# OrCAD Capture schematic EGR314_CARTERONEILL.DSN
size B; title: Audio Sensor Team 203 Carter ONeill
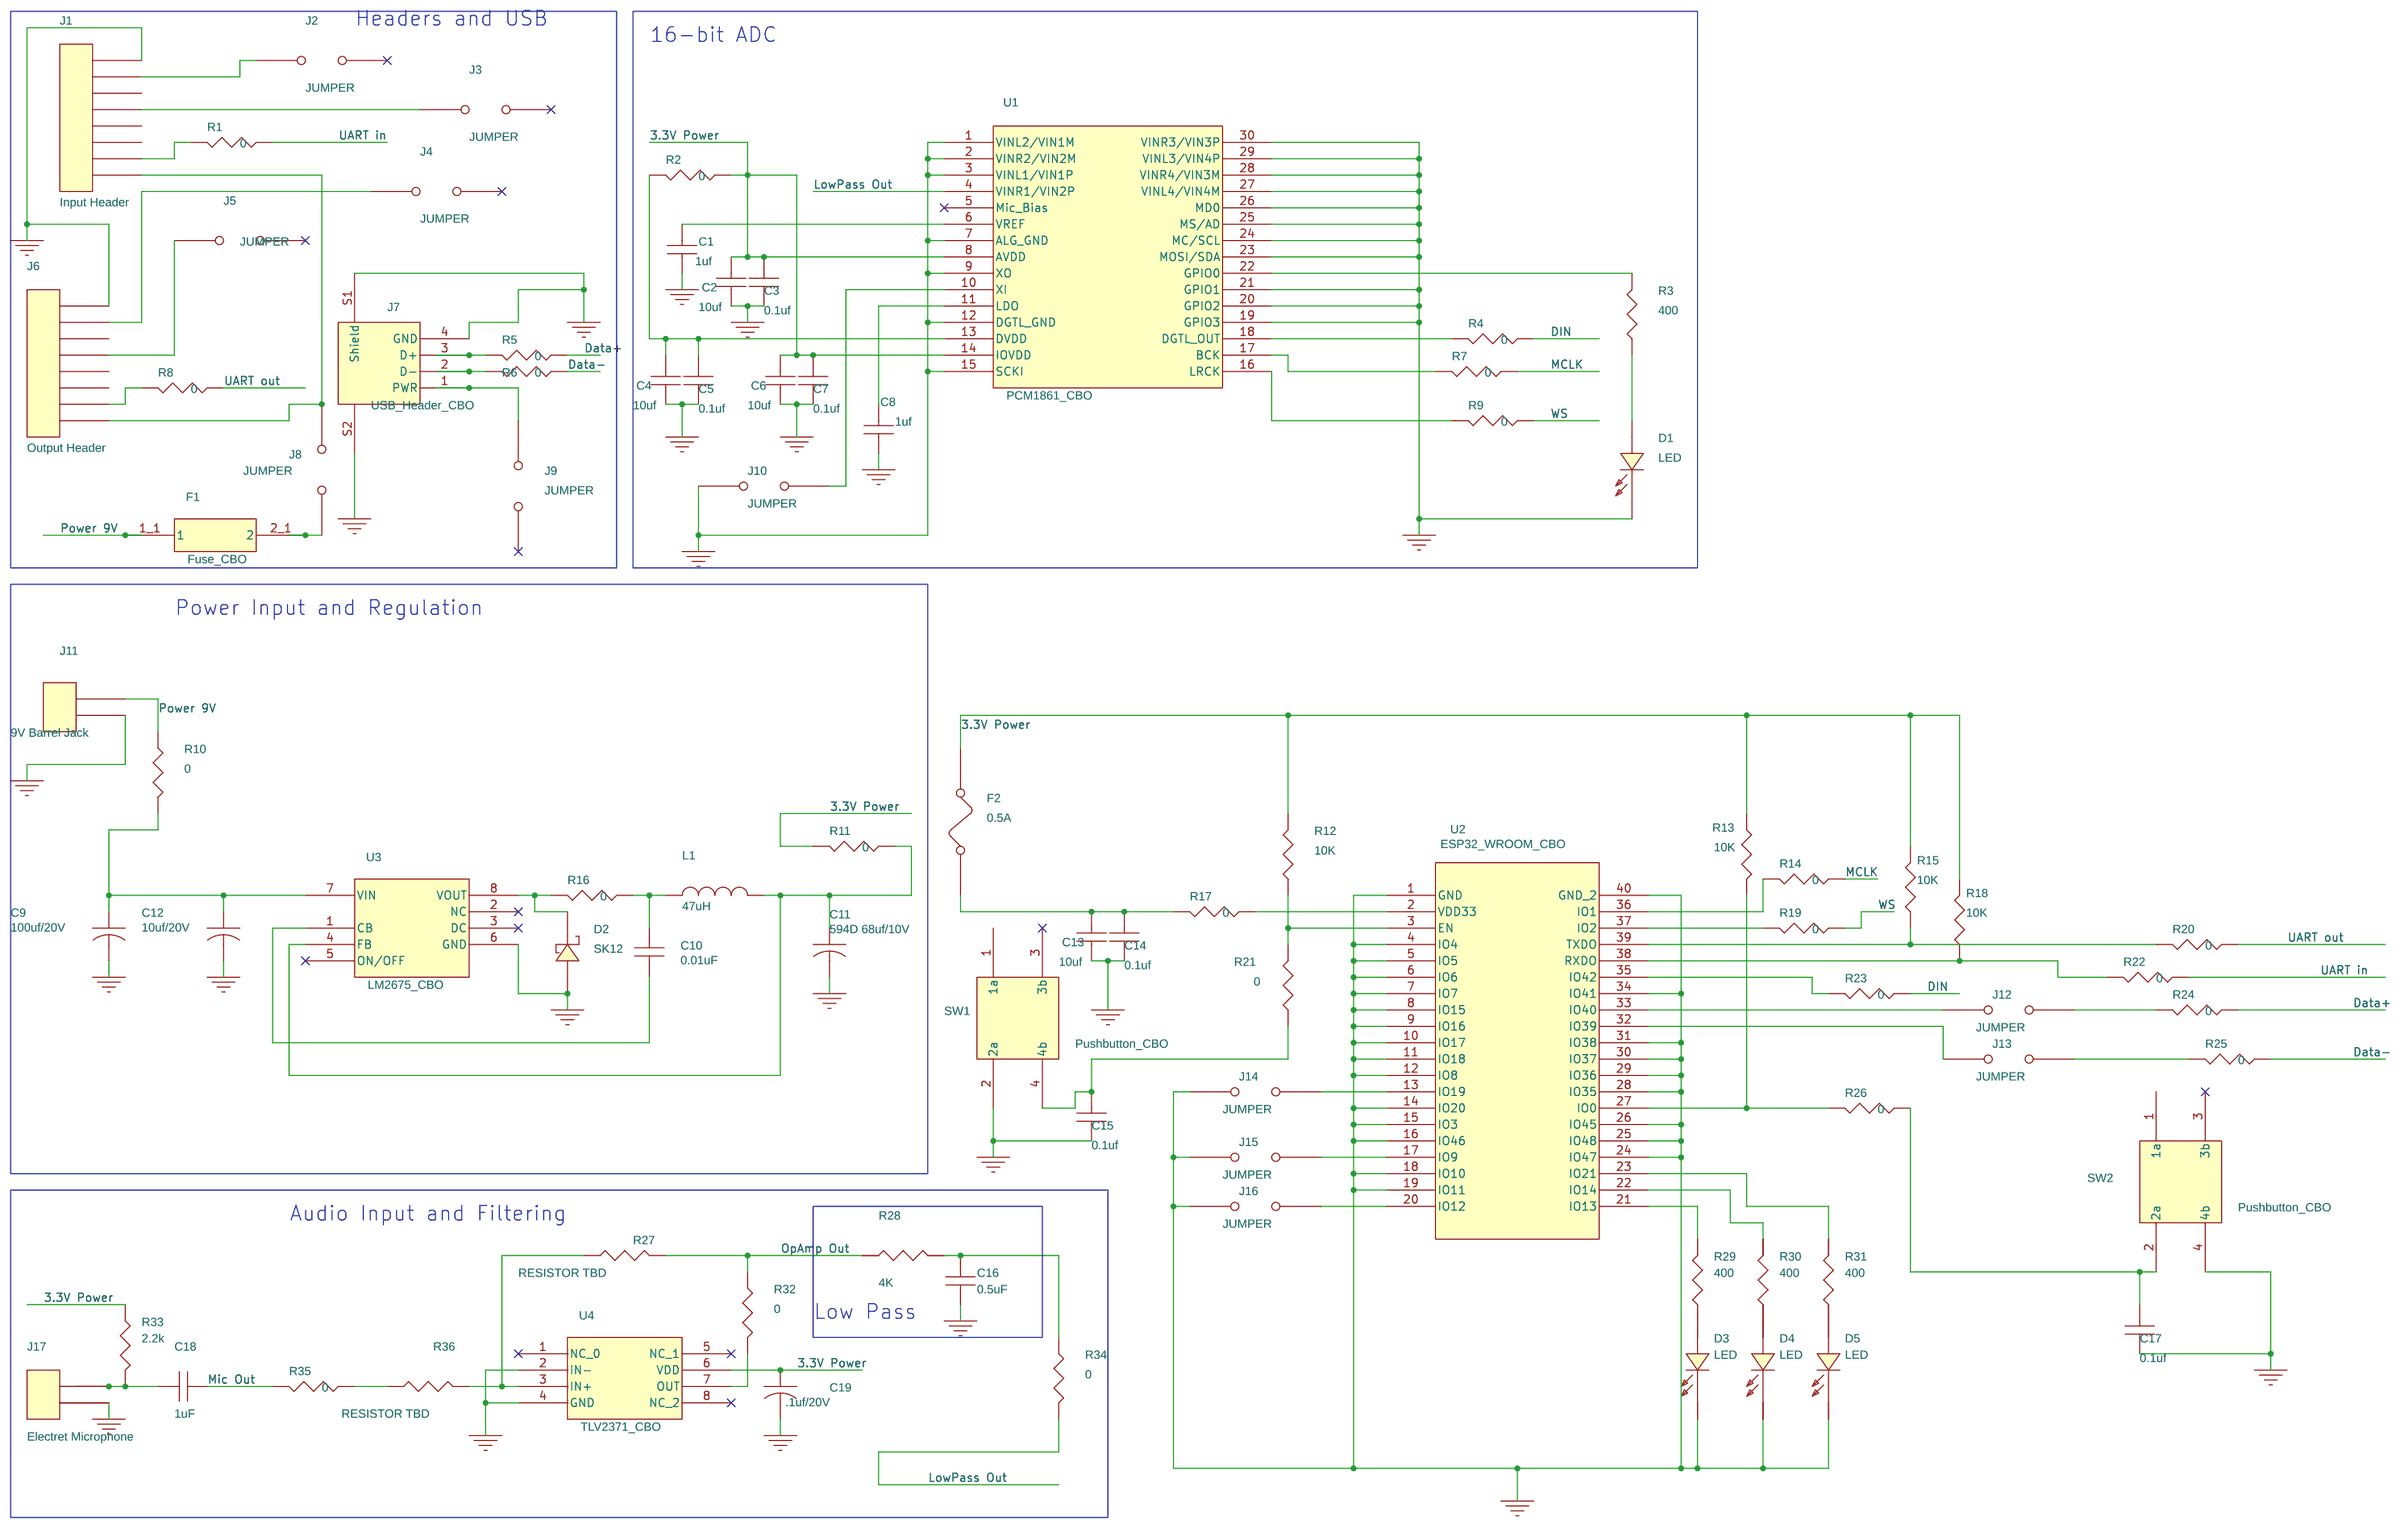
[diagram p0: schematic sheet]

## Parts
C1  1uf  [smc0805]
C2  10uf  [smc0805]
C3  0.1uf  [smc0805]
C4  10uf  [smc0805]
C5  0.1uf  [smc0805]
C6  10uf  [smc0805]
C7  0.1uf  [smc0805]
C8  1uf  [smc0805]
C9  100uf/20V  [smc0805]
C10  0.01uF  [smc0805]
C11  594D 68uf/10V  [smc0805]
C12  10uf/20V  [smc0805]
C13  10uf  [smc0805]
C14  0.1uf  [smc0805]
C15  0.1uf  [smc0805]
C16  0.5uF  [smc0805]
C17  0.1uf  [smc0805]
C18  1uF  [smc0805]
C19  .1uf/20V  [smc0805]
D1  LED  [smr0805]
D2  SK12  [smr0805]
D3  LED  [smr0805]
D4  LED  [smr0805]
D5  LED  [smr0805]
F1  Fuse_CBO  [FUSE_3587-20TR]
F2  0.5A  [smr0805]
J1  Input Header  [jumper8]
J2  JUMPER  [jumper2]
J3  JUMPER  [jumper2]
J4  JUMPER  [jumper2]
J5  JUMPER  [jumper2]
J6  Output Header  [jumper8]
J7  USB_Header_CBO  [ONSHORE_USB-A1VSB6]
J8  JUMPER  [jumper2]
J9  JUMPER  [jumper2]
J10  JUMPER  [jumper2]
J11  9V Barrel Jack  [CONN2_770966-2]
J12  JUMPER  [jumper2]
J13  JUMPER  [jumper2]
J14  JUMPER  [jumper2]
J15  JUMPER  [jumper2]
J16  JUMPER  [jumper2]
J17  Electret Microphone  [CONN2_770966-2]
L1  47uH  [smr0805]
R1  0  [smr0805]
R2  0  [smr0805]
R3  400  [smr0805]
R4  0  [smr0805]
R5  0  [smr0805]
R6  0  [smr0805]
R7  0  [smr0805]
R8  0  [smr0805]
R9  0  [smr0805]
R10  0  [smr0805]
R11  0  [smr0805]
R12  10K  [smr0805]
R13  10K  [smr0805]
R14  0  [smr0805]
R15  10K  [smr0805]
R16  0  [smr0805]
R17  0  [smr0805]
R18  10K  [smr0805]
R19  0  [smr0805]
R20  0  [smr0805]
R21  0  [smr0805]
R22  0  [smr0805]
R23  0  [smr0805]
R24  0  [smr0805]
R25  0  [smr0805]
R26  0  [smr0805]
R27  RESISTOR TBD  [smr0805]
R28  4K  [smr0805]
R29  400  [smr0805]
R30  400  [smr0805]
R31  400  [smr0805]
R32  0  [smr0805]
R33  2.2k  [smr0805]
R34  0  [smr0805]
R35  0  [smr0805]
R36  RESISTOR TBD  [smr0805]
SW1  Pushbutton_CBO  [SW_TL3305AF260QG]
SW2  Pushbutton_CBO  [SW_TL3305AF260QG]
U1  PCM1861_CBO  [SOP50P640X120-30N]
U2  ESP32_WROOM_CBO  [XCVR_ESP32-S3-WROOM-1-N4]
U3  LM2675_CBO  [SOIC127P599X175-8N]
U4  TLV2371_CBO  [SOIC127P599X175-8N]

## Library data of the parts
C1-C8 C13-C18 = CAP_NP
C9 C11 C12 C19 = CAP
C10 = CAPACITOR_NON-POL
D1 D3-D5 = LED
D2 = DIODE_SCHOTTKY
F1 = Fuse_CBO
F2 = FUSE
J1 J6 = CON8
J2-J5 J8-J10 J12-J16 = JUMPER
J7 = USB_Header_CBO
J11 J17 = CON2
L1 = INDUCTOR
R1-R36 = RESISTOR
SW1 SW2 = Pushbutton_CBO
U1 = PCM1861_CBO
U2 = ESP32_WROOM_CBO
U3 = LM2675_CBO
U4 = TLV2371_CBO

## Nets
3.3V Power: C2.2 C3.2 C6.2 C7.2 C19.1 F2.1 R2.1 R11.2 R12.2 R13.2 R15.2 R18.2 R33.1 U1.8(AVDD) U1.14(IOVDD) U4.6(VDD)
GND_POWER: C1.1 C2.1 C3.1 C4.1 C5.1 C6.1 C7.1 C8.1 C9.2 C11.2 C12.2 C13.1 C14.1 C15.1 C16.1 C17.1 C19.2 D1.1(CATHODE) D2.1(ANODE) D3.1(CATHODE) D4.1(CATHODE) D5.1(CATHODE) J1.8 J6.8 J7.4(GND) J7.S1(Shield) J7.S2 J10.2 J11.2 J14.2 J15.2 J16.2 J17.2 SW1.2(2a) SW2.4(4b) U1.1(VINL2/VIN1M) U1.2(VINR2/VIN2M) U1.3(VINL1/VIN1P) U1.7(ALG_GND) U1.9(XO) U1.12(DGTL_GND) U1.15(SCKI) U1.19(GPIO3) U1.20(GPIO2) U1.21(GPIO1) U1.23(MOSI/SDA) U1.24(MC/SCL) U1.25(MS/AD) U1.26(MD0) U1.27(VINL4/VIN4M) U1.28(VINR4/VIN3M) U1.29(VINL3/VIN4P) U1.30(VINR3/VIN3P) U2.1(GND) U2.4(IO4) U2.5(IO5) U2.6(IO6) U2.7(IO7) U2.8(IO15) U2.9(IO16) U2.10(IO17) U2.11(IO18) U2.12(IO8) U2.14(IO20) U2.15(IO3) U2.16(IO46) U2.18(IO10) U2.19(IO11) U2.24(IO47) U2.25(IO48) U2.26(IO45) U2.28(IO35) U2.29(IO36) U2.30(IO37) U2.31(IO38) U2.34(IO41) U2.40(GND_2) U3.6(GND) U4.2(IN-) U4.4(GND)
Data+: R5.1 R24.1
Data-: R6.1 R25.1
DIN: R4.1 R23.1
LowPass Out: R34.2 U1.4(VINR1/VIN2P)
MCLK: R7.1 R14.1
Mic Out: C18.1 R35.2
OpAmp Out: R27.1 R28.1 R32.1
Power 9V: F1.1_1(1) J11.1 R10.1
UART in: R1.1 R22.1
UART out: R8.1 R20.1
WS: R9.1 R19.1
N00606: C9.1 C12.1 R10.2 U3.7(VIN)
N00781: D2.2(CATHODE) R16.2 U3.8(VOUT)
N00783: C10.1 L1.1 R16.1
N00788: C10.2 U3.1(CB)
N00918: C11.1 L1.2 R11.1 U3.4(FB)
N07817: J1.1 J6.1 J8.2
N09843: J6.2 R8.2
N21699: J1.2 R1.2
N22060: F1.2_1(2) J8.1
N22626: J7.2(D-) R6.2
N22652: J7.3(D+) R5.2
N22917: J7.1(PWR) J9.2
N24434: J1.7 J2.2
N24454: J4.2 J6.7
N24458: J5.2 J6.5
N24715: J1.5 J3.2
N26680: C18.2 J17.1 R33.2
N29485: R27.2 R36.1 U4.3(IN+)
N29573: R32.2 U4.7(OUT)
N34669: C16.2 R28.2 R34.1
N36501: C4.2 C5.2 R2.2 U1.13(DVDD)
N37158: C1.2 U1.6(VREF)
N37386: C8.2 U1.11(LDO)
N38649: J10.1 U1.10(XI)
N39459: R9.2 U1.16(LRCK)
N39468: R7.2 U1.17(BCK)
N39483: R4.2 U1.18(DGTL_OUT)
N40504: D1.2(ANODE) R3.1
N40674: R3.2 U1.22(GPIO0)
N41571: R15.1 R20.2 U2.39(TXDO)
N41575: R18.1 R22.2 U2.38(RXDO)
N41673: C13.2 C14.2 F2.2 R17.2
N43009: R12.1 R21.1 U2.3(EN)
N43015: C15.2 R21.2 SW1.4(4b)
N44695: R14.2 U2.36(IO1)
N44721: R19.2 U2.37(IO2)
N46155: R23.2 U2.35(IO42)
N46205: J16.1 U2.20(IO12)
N46209: J15.1 U2.17(IO9)
N46676: J14.1 U2.13(IO19)
N51510: R31.2 U2.23(IO21)
N51528: R30.2 U2.22(IO14)
N51546: R29.2 U2.21(IO13)
N53013: J12.1 R24.2
N53017: J13.1 R25.2
N53033: J12.2 U2.33(IO40)
N53151: R13.1 R26.2 U2.27(IO0)
N53160: C17.2 R26.1 SW2.2(2a)
N53179: J13.2 U2.32(IO39)
N71514: R35.1 R36.2
N73812: R17.1 U2.2(VDD33)
N151310: D4.2(ANODE) R30.1
N151311: D3.2(ANODE) R29.1
N151312: D5.2(ANODE) R31.1

Not connected (* = marked no-connect by the designer): J1 3 4 6; J2 1*; J3 1*; J4 1*; J5 1*; J6 3 4 6; J9 1*; SW1 1(1a) 3(3b)*; SW2 1(1a) 3(3b)*; U1 5(Mic_Bias)*; U3 2(NC)* 3(DC)* 5(ON/OFF)*; U4 1(NC_0)* 5(NC_1)* 8(NC_2)*

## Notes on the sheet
- Headers and USB
- 16-bit ADC
- Power Input and Regulation
- Audio Input and Filtering
- Low Pass
